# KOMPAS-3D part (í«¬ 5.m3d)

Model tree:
1. Эскиз:1
2. Операция выдавливания:1
     Расстояние 1 = 3
3. Эскиз:2
4. Операция выдавливания:2
     Расстояние 1 = 78
5. Эскиз:3
6. Операция выдавливания:3
     Расстояние 1 = 3
7. Эскиз:4
8. Операция выдавливания:4
     Расстояние 1 = 4
9. Эскиз:5
10. Операция выдавливания:5
     Расстояние 1 = 4
